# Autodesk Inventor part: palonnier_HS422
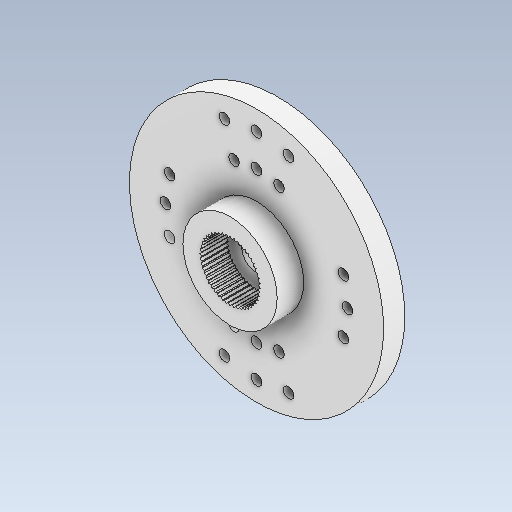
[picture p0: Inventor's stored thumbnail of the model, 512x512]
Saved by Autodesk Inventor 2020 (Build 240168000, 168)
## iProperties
Created: 2012-04
Part Number: palonnier_HS422
Material: Générique
Document SubType Name: Modeling
Designer: bruno
Density: 1 g/cm^3
Appearance: Par défaut
Author: bruno
Sending System: SolidWorks 2016
Last Author: Prof
Last Saved: 2018-11-12
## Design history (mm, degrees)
feature "Extru.-Mince1"
node "Solide1"
